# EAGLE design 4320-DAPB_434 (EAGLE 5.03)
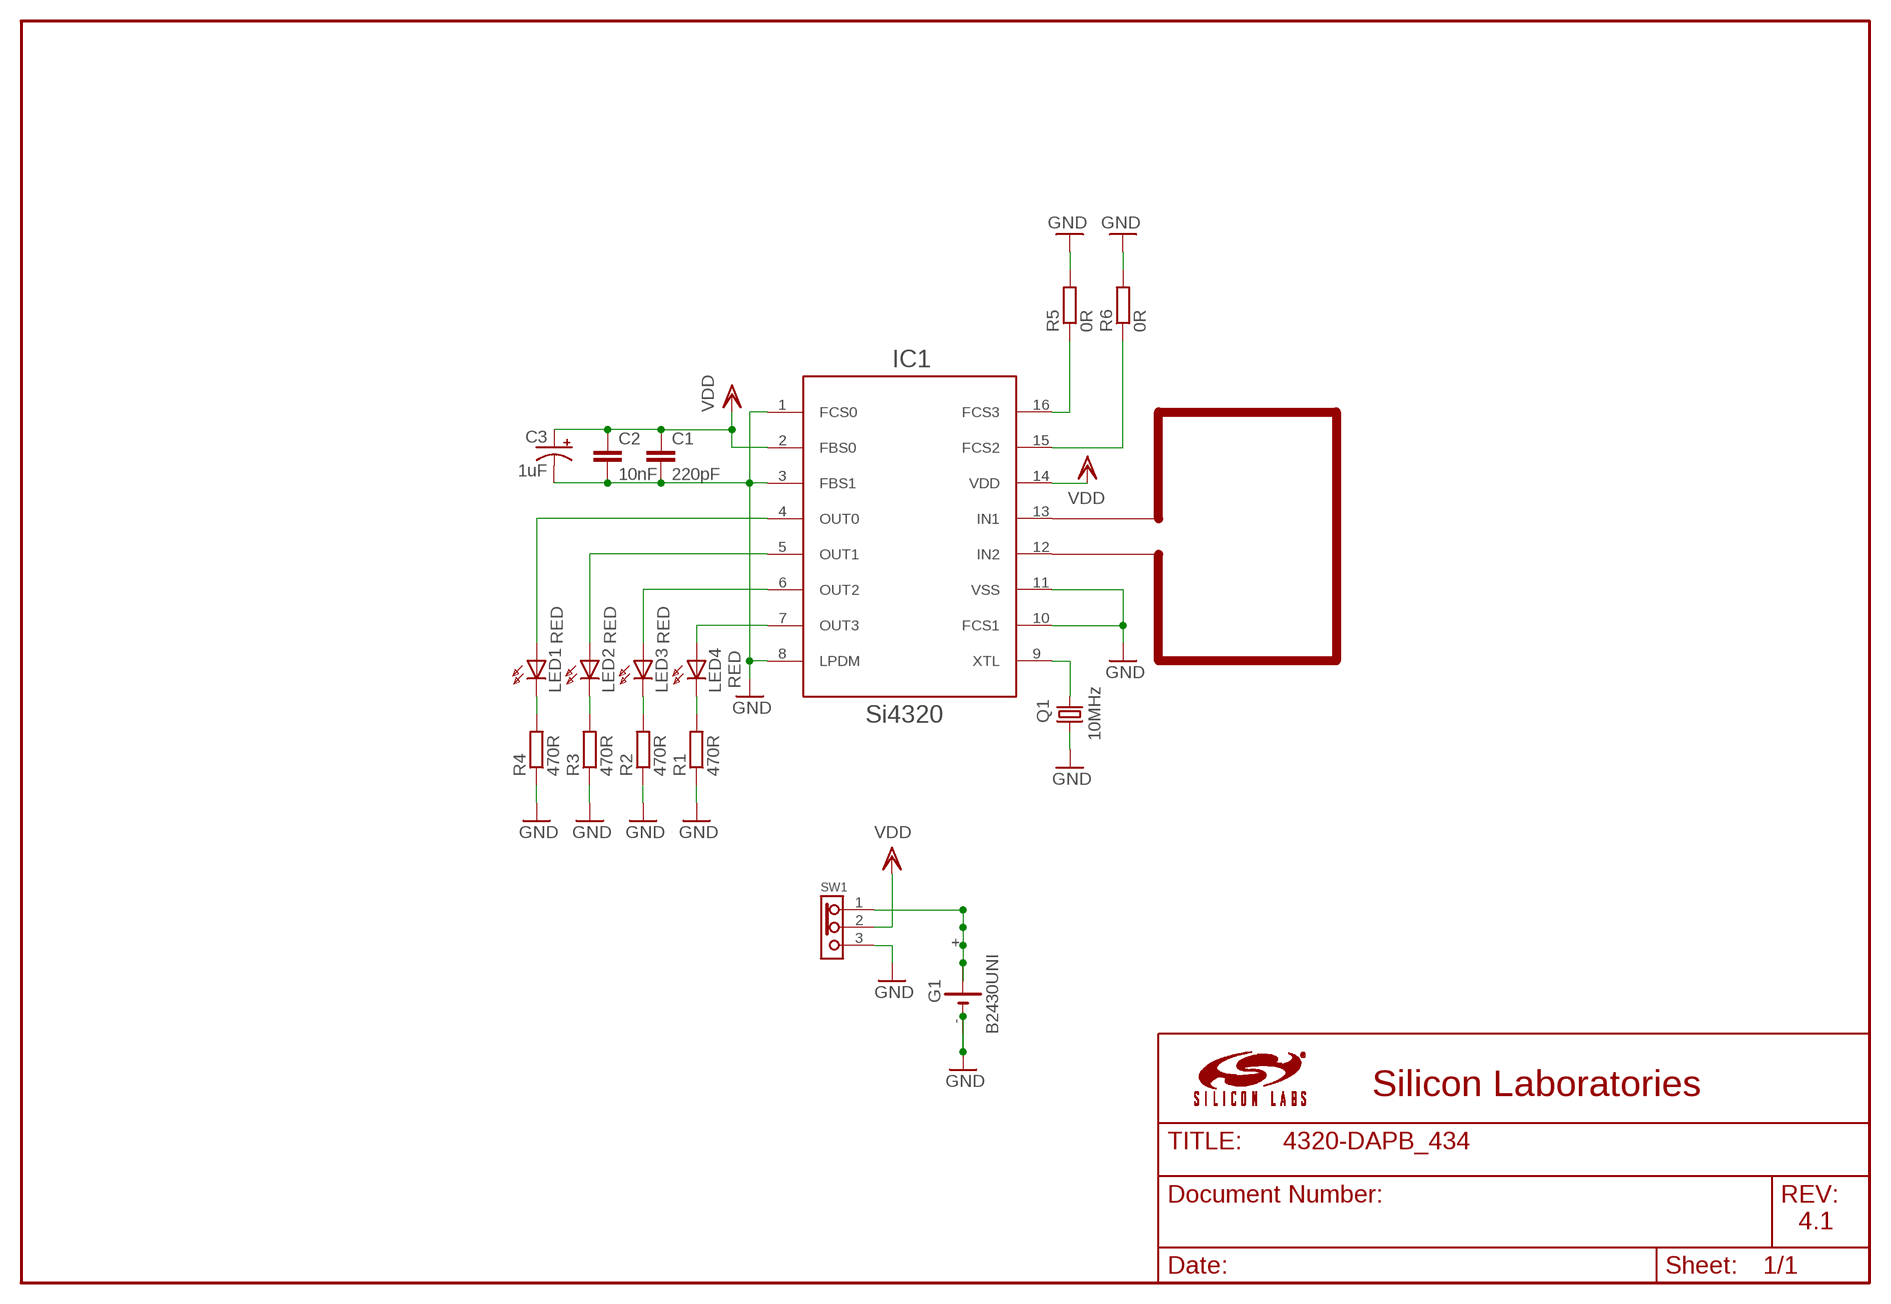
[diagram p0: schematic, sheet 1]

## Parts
C1  220pF  C-EUC0603K  [C0603K]
C2  10nF  C-EUC0603K  [C0603K]
C3  1uF  CPOL-USCT3216  [CT3216]
G1  B2430UNI  [B2430UNI]
IC1  Si4320  RITA-STANDALONE  [TSSOP-16]
LED1  RED  LED3MM  [LED3MM]
LED2  RED  LED3MM  [LED3MM]
LED3  RED  LED3MM  [LED3MM]
LED4  RED  LED3MM  [LED3MM]
Q1  10MHz  CRYSTAL-4PINSX-5032_NEW  [QUARTZ_SIWARD_5032_NEW]
R1  470R  R-EU_R0603  [R0603]
R2  470R  R-EU_R0603  [R0603]
R3  470R  R-EU_R0603  [R0603]
R4  470R  R-EU_R0603  [R0603]
R5  0R  R-EU_R0603  [R0603]
R6  0R  R-EU_R0603  [R0603]
SW1  SWITCH-T106EG1218  [SWITCH-EG1218]

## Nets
GND: C1.2 C2.2 C3.- G1.- G1.-@1(-) IC1.1(FCS0) IC1.3(FBS1) IC1.8(LPDM) IC1.10(FCS1) IC1.11(VSS) Q1.1 R1.1 R2.1 R3.1 R4.1 R5.2 R6.2 SW1.3
N$1: IC1.7(OUT3) LED4.A
N$2: IC1.6(OUT2) LED3.A
N$3: IC1.5(OUT1) LED2.A
N$4: IC1.4(OUT0) LED1.A
N$5: LED4.K(C) R1.2
N$6: LED3.K(C) R2.2
N$7: LED2.K(C) R3.2
N$8: LED1.K(C) R4.2
N$10: IC1.9(XTL) Q1.3
N$11: IC1.16(FCS3) R5.1
N$12: IC1.15(FCS2) R6.1
S$1: G1.+ G1.+@1(+) G1.+@2(+) G1.+@3(+) G1.+@4(+) SW1.1
VDD: C1.1 C2.1 C3.+ IC1.2(FBS0) IC1.14(VDD) SW1.2
Unconnected: IC1.12(IN2) IC1.13(IN1)

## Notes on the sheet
- Silicon Laboratories
- 4.1

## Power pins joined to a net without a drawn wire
GND: Q1.2(GND) Q1.4(GND)

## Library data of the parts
C1 C2 = rcl:C-EU: CAPACITOR, European symbol
C3 = rcl:CPOL-US: POLARIZED CAPACITOR, American symbol
G1 = battery:B2430UNI: LI BATTERY
IC1 = lve:RITA-STANDALONE
LED1-LED4 = led:LED: LED
Q1 = lve:CRYSTAL-4PIN
R1-R6 = rcl:R-EU_: RESISTOR, European symbol
SW1 = lve:SWITCH-T106

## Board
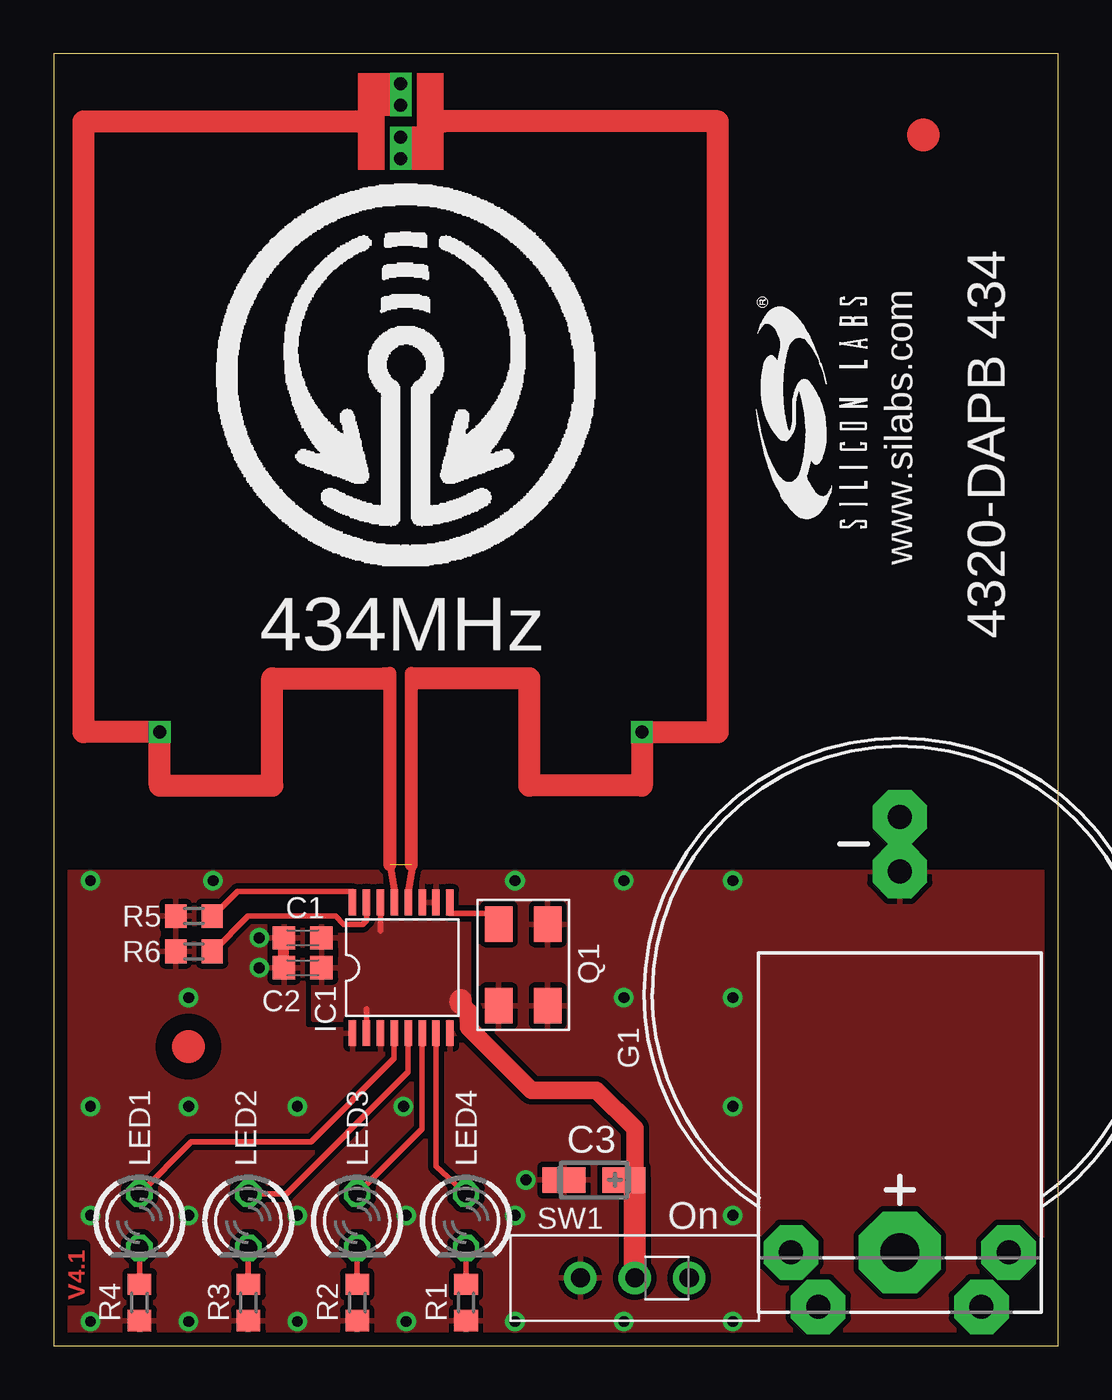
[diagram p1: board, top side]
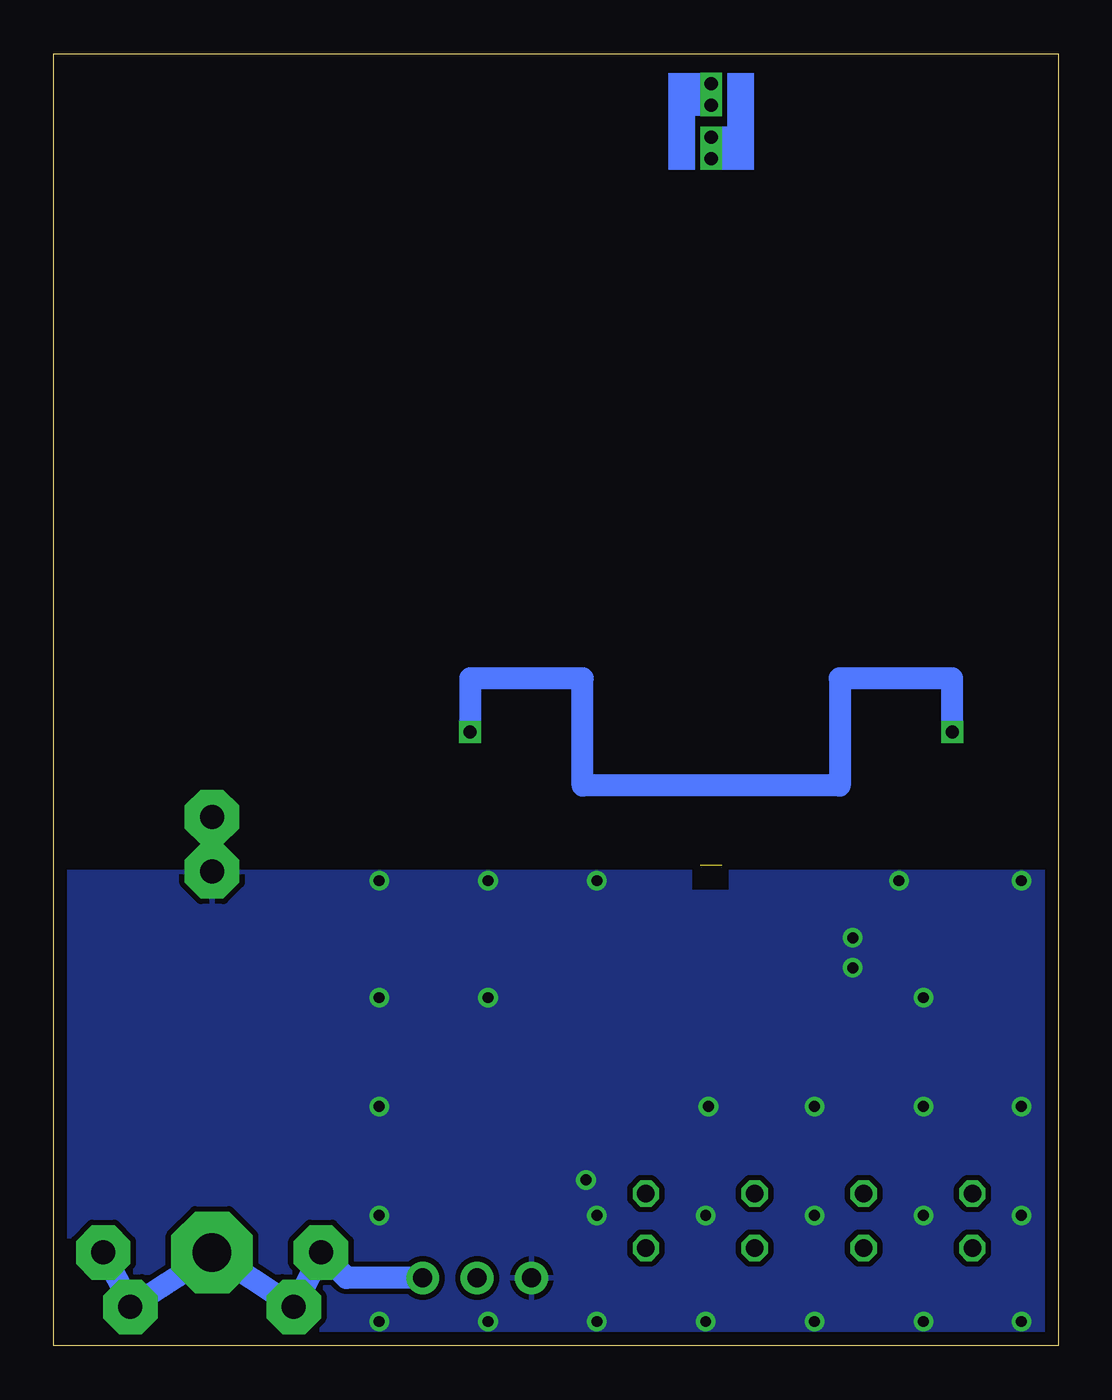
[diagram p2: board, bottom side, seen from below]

Size 46.89 x 60.3 mm. Coordinates in mm from the lower left corner, seen from the top.
Outline: 46.89,0 46.89,60.3 0,60.3 0,0 46.89,0
Copper layers (1*16): Top 0.0356mm / dielectric 1.5011mm / Bottom 0.0356mm
Design rules "default_INTEGRATION *": minimum track width 10mil, minimum drill 20mil, track to track 10mil, track to pad 10mil, pad to pad 10mil, via to via 10mil, smd to smd 0mil, copper to edge 25mil, drill to drill 8mil, minimum pad ring 8mil, minimum via ring 8mil, stop-mask expansion 4mil, vias tented up to drill 24mil, thermal gap 10mil
tRestrict: area 14.8,14 to 15.1,15.2; area 15.4,14 to 15.7,15.2; area 14.1,14 to 14.4,15.2; area 18,14 to 18.3,15.2; area 18,20.1 to 18.3,21.3; area 16.7,20.1 to 17,21.1; area 14.8,20.1 to 15.1,21.3; area 15.4,21.3 to 17.1,22.2; 4 lines
bRestrict: area 15.4,21.3 to 17.1,22.2

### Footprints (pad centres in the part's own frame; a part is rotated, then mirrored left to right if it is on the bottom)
C0603K = smd 1.05 x 1.08: 1 -0.875,0; 2 0.875,0
CT3216 = smd 2 x 1.2: + -1.4,0; - 1.4,0
B2430UNI = drill 1.118 pad 2.54 octagon: + 3.81,14.605; +@1 -3.81,14.605; +@2 -5.08,12.065; +@3 5.08,12.065; - 0,-5.715; -@1 0,-8.255 | drill 1.803 pad 3.81 octagon: +@4 0,12.065
TSSOP-16 = smd 1.2 x 0.35: 1 -3.107,2.223; 2 -3.107,1.573; 3 -3.107,0.922; 4 -3.107,0.273; 5 -3.107,-0.378; 6 -3.107,-1.028; 7 -3.107,-1.677; 8 -3.107,-2.328; 9 2.993,-2.328; 10 2.993,-1.677; 11 2.993,-1.028; 12 2.993,-0.378; 13 2.993,0.273; 14 2.993,0.922; 15 2.993,1.573; 16 2.993,2.223
LED3MM = drill 0.813 octagon: A -1.27,0; K 1.27,0
QUARTZ_SIWARD_5032_NEW = smd 1.651 x 1.27: 1 -1.905,-1.143; 2 1.905,-1.143; 3 1.905,1.143; 4 -1.905,1.143
R0603 = smd 1 x 1.1: 1 -0.85,0; 2 0.85,0
SWITCH-EG1218 = drill 0.889 pad 1.524 round: 1 -2.54,0; 2 0,0; 3 2.54,0

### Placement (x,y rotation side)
C1  11.63,19.05 180 top
C2  11.63,17.65 180 top
C3  25.22,7.74 180 top
G1  39.49,16.43 180 top
IC1  16.17,17.7 90 top
LED1  4.01,5.84 270 top
LED2  9.09,5.84 270 top
LED3  14.17,5.84 270 top
LED4  19.25,5.84 270 top
Q1  21.92,17.78 90 top
R1  19.25,2.03 90 top
R2  14.17,2.03 90 top
R3  9.09,2.03 90 top
R4  4.01,2.03 90 top
R5  6.55,20.06 180 top
R6  6.55,18.41 180 top
SW1  27.12,3.17 180 top
U$1  [SILABS_LOGO]  38.43,37.21 90 top
U$3  [RECEIVE-ICON]  16.46,45.71 0 top
U$4  [FIDUCIAL]  40.59,56.51 0 top
U$5  [FIDUCIAL]  6.3,13.96 0 top

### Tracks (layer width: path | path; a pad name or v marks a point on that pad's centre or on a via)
GND  (via drill 0.51 pad 0.76)
  Top 0.508: G1.- G1.-@1 | 10.74,17.78 10.74,17.65 | 10.74,17.78 10.74,19.05 | C2.2 10.75,17.78 10.74,17.78
  other vias: 1.72,1.14 1.72,11.17 1.72,6.09 6.3,6.09 11.38,6.09 6.3,1.14 11.38,1.14 6.3,11.17 11.38,11.17 6.3,16.25 7.44,21.71 16.46,1.14 16.46,6.09 16.33,11.17 21.54,6.09 21.54,1.14 26.62,1.14 31.7,1.14 31.7,6.09 31.7,11.17 31.7,16.25 21.54,21.71 26.62,16.25 26.62,21.71 31.7,21.71 9.6,19.05 1.72,21.71 9.6,17.65 22.04,7.74
  pour Top (rank 2): -0.04,-0.01 -0.04,22.09 47.05,22.09 47.05,-0.01
  pour Bottom (rank 6): -0.04,22.09 47.05,22.09 47.05,-0.01 -0.04,-0.01
N$1
  Top 0.254: IC1.7 17.85,8.38 LED4.A
N$2
  Top 0.254: IC1.6 17.2,10.14 LED3.A
N$3
  Top 0.254: IC1.5 16.55,12.79 10.87,7.11 LED2.A
N$4
  Top 0.254: IC1.4 15.9,13.41 12.01,9.52 6.42,9.52 LED1.A
N$5
  Top 0.254: 19.25,4.59 LED4.K R1.2
N$6
  Top 0.254: 14.17,4.69 LED3.K | R2.2 14.17,4.69 | 14.17,4.69 14.22,4.69
N$7
  Top 0.254: R3.2 LED2.K
N$8
  Top 0.254: 4.01,4.59 LED1.K R4.2
N$9
  Top 0.33: 16.72,22.27 16.54,21.19
N$10
  Top 0.254: 18.5,20.39 18.49,20.39 | 18.5,20.39 IC1.9 | 18.5,20.39 18.5,20.19 20.52,20.19 Q1.3
N$11
  Top 0.254: IC1.16 13.95,21.2 8.58,21.2 7.44,20.06 R5.1
N$12
  Top 0.254: IC1.15 14.6,19.86 14.42,19.68 13.54,19.68 13.15,20.06 9.09,20.06 7.44,18.41 R6.1
S$1
  Bottom 1.016: G1.+@2 43.25,1.9 G1.+@1 39.44,4.31 G1.+@4 35.76,1.9 G1.+ 34.36,4.31 G1.+@3 33.22,3.17 SW1.1
S$31
  Top 0.33: 15.72,22.27 15.91,21.19
S$158  (1 unrouted)
  Top 0.61: 15.7,22.45 15.7,31.4 | 16.7,22.45 16.7,31.4
S$159  (via drill 0.61 pad 0.41)
  other vias: 16.2,56.4
S$160  (via drill 0.61 pad 0.41)
  other vias: 16.2,57.9
S$164  (via drill 0.61, 0.61 pad 0.41)
  Top 1.016: 14.2,57.15 1.4,57.15 1.4,28.65 v4.95,28.65 4.95,26.15 10.2,26.15 | 18.2,57.15 31,57.15 31,28.65 v27.45,28.65 27.45,26.15 22.2,26.15 22.2,31.15 16.95,31.15
  Bottom 1.016: v4.95,28.65 4.95,31.15 10.2,31.15 10.2,26.15 22.2,26.15 22.2,31.15 27.45,31.15 v27.45,28.65
S$165
  Top 1.016: 15.45,31.15 10.2,31.15 10.2,26.15
S$168  (via drill 0.61 pad 0.41)
  other vias: 16.2,55.4
S$169  (via drill 0.61 pad 0.41)
  other vias: 16.2,58.9
VDD
  Top 0.254: IC1.2 14.6,15.73 | 15.25,19.37 15.25,19.55 IC1.14
  Top 0.813: 19,16 19.38,15.62 19.38,14.85 22.3,11.93 25.35,11.93 27.12,10.15 27.12,7.74 27.12,7.36
  Top 1.016: SW1.2 27.12,7.74 C3.+ | 19,16 19,16.12
  pour Top: 12.14,15.23 12.14,20.06 19.38,20.06 19.38,15.23
(copper drawn outside any net)
  shapes: Bottom area x5, Top area x6

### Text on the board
Top: V4.1
tPlace: www.silabs.com | 4320-DAPB 434 | 434MHz | On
